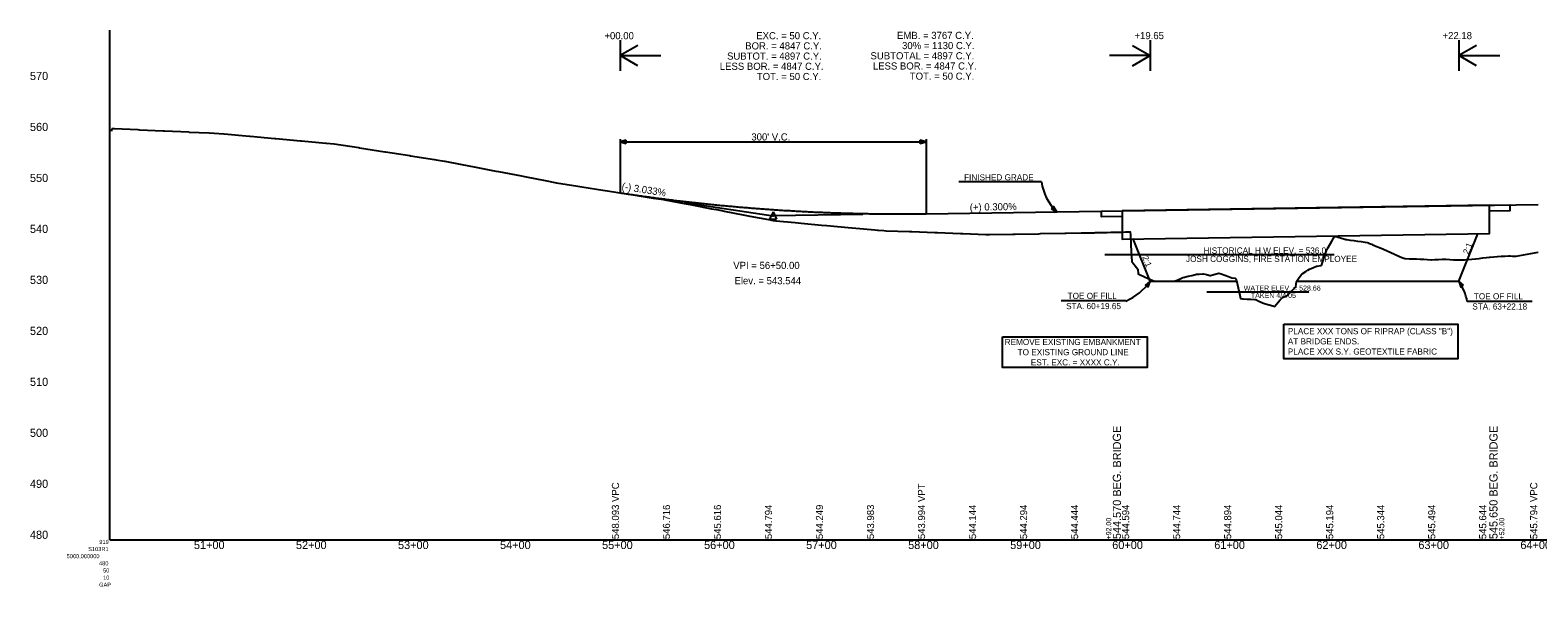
# Model space of a CAD drawing. Extents: x 1961504 to 1964196, y 1107046 to 1115093.
# Drawn here: x 1961506 to 1962983, y 1107046 to 1107593 of the extents above; entities that cross this region are included whole.
import ezdxf

# ---------------------------------------------------------------- set-up
doc = ezdxf.new("R2010")
doc.units = 0
for name, color, linetype in [('Level 40', 7, 'Continuous'), ('Level 41', 7, 'Continuous'), ('Level 42', 7, 'Continuous'), ('Level 43', 7, 'Continuous'), ('Level 45', 7, 'Continuous'), ('Level 49', 7, 'Continuous'), ('Level 58', 7, 'Continuous'), ('Level 63', 7, 'Continuous')]:
    doc.layers.add(name, color=color, linetype=linetype)

msp = doc.modelspace()

# ---------------------------------------------------------------- linework, layer by layer
at = {"layer": 'Level 40'}
for points in [[(1961585.6, 1107493.6), (1961585.8, 1107494.5), (1961586, 1107496.1), (1961588.4, 1107496), (1961611, 1107495), (1961612.8, 1107494.9), (1961636, 1107493.8), (1961637.2, 1107493.8), (1961661, 1107492.7), (1961661.5, 1107492.6), (1961681.2, 1107491.7), (1961686, 1107491.5), (1961686.1, 1107491.5), (1961695.5, 1107491), (1961695.9, 1107491), (1961720.5, 1107488.7), (1961721.1, 1107488.6), (1961745.5, 1107486.4), (1961746.3, 1107486.3), (1961770.4, 1107484.1), (1961771.5, 1107484), (1961795.4, 1107481.8), (1961795.9, 1107481.8), (1961803.4, 1107481.1), (1961827.7, 1107477.3), (1961828.4, 1107477.2), (1961853.3, 1107473.3), (1961853.3, 1107473.3), (1961853.7, 1107473.3), (1961877.7, 1107469.5), (1961878.4, 1107469.4), (1961902, 1107465.6), (1961903.4, 1107465.4), (1961911.6, 1107464.1), (1961912.1, 1107464), (1961913.7, 1107463.7), (1961937.1, 1107459.2), (1961939.2, 1107458.8), (1961962.1, 1107454.3), (1961964.7, 1107453.8), (1961987, 1107449.5), (1961990.2, 1107448.9), (1962012, 1107444.7), (1962019.8, 1107443.2), (1962021.4, 1107442.8), (1962042.3, 1107439.6), (1962046.4, 1107438.9), (1962067, 1107435.7), (1962071.5, 1107434.9), (1962091.6, 1107431.8), (1962096.5, 1107431), (1962116.3, 1107427.9), (1962121.5, 1107427), (1962126.4, 1107426.3), (1962127.5, 1107426.1), (1962146.7, 1107422.4), (1962152.4, 1107421.4), (1962154.2, 1107421.1), (1962173.5, 1107417.4), (1962178.4, 1107416.6), (1962183, 1107415.7), (1962185.7, 1107414.9), (1962204.4, 1107411.3), (1962210.8, 1107410.2), (1962229.2, 1107406.7), (1962233.9, 1107405.9), (1962236.4, 1107405.5), (1962255.4, 1107403.8), (1962261.4, 1107403.2), (1962281.3, 1107401.4), (1962286.3, 1107400.9), (1962307.4, 1107399.1), (1962311.3, 1107398.7), (1962333.4, 1107396.7), (1962336.2, 1107396.5), (1962336.7, 1107396.4), (1962342.3, 1107395.9), (1962344.7, 1107395.8), (1962367.3, 1107395), (1962369.7, 1107394.9), (1962392.3, 1107394), (1962394.7, 1107394), (1962417.3, 1107393.1), (1962419.7, 1107393), (1962442.3, 1107392.2), (1962442.8, 1107392.1), (1962445.9, 1107392), (1962468.8, 1107392.4), (1962470.9, 1107392.5), (1962494.1, 1107392.9), (1962495.9, 1107393), (1962519.5, 1107393.4), (1962520.9, 1107393.4), (1962535.7, 1107393.7), (1962539.3, 1107393.8), (1962542.9, 1107393.8), (1962544.8, 1107393.9), (1962545.9, 1107393.9), (1962545.9, 1107393.9), (1962546.5, 1107393.9), (1962548.4, 1107393.9)], [(1962548.4, 1107393.9), (1962549.5, 1107394), (1962550.2, 1107394), (1962553.8, 1107394), (1962557.4, 1107394.1), (1962561, 1107394.2), (1962564.6, 1107394.3), (1962568.2, 1107394.3), (1962571.8, 1107394.4), (1962573.4, 1107394.4), (1962574.2, 1107394.5), (1962575.4, 1107394.5), (1962579.1, 1107394.6), (1962582.7, 1107394.6), (1962583.7, 1107394.6), (1962583.8, 1107394.7), (1962583.9, 1107391.5), (1962584.2, 1107381.5), (1962585.3, 1107365.4), (1962586.3, 1107364.3), (1962589.9, 1107359.8), (1962591.2, 1107358.1), (1962591.5, 1107353.4), (1962593.5, 1107352.4), (1962597.1, 1107350.8), (1962598.5, 1107350.1), (1962600.7, 1107349.2), (1962604.3, 1107347.8), (1962606.9, 1107346.7), (1962607.9, 1107346.4), (1962608, 1107346.4), (1962611.6, 1107346.3), (1962615.2, 1107346.3), (1962618.8, 1107346.3), (1962622.4, 1107346.3), (1962626, 1107346.2), (1962626.8, 1107346.2), (1962627.9, 1107346.6), (1962629.6, 1107347.4), (1962633.2, 1107349.1), (1962635.4, 1107350), (1962636.8, 1107350.4), (1962640.4, 1107351.2), (1962644.1, 1107352), (1962647.7, 1107352.9), (1962648.7, 1107353.1), (1962651.3, 1107353.3), (1962654.9, 1107353.6), (1962655.4, 1107353.6), (1962658.5, 1107352.8), (1962662.1, 1107351.9), (1962662.3, 1107351.9), (1962665.7, 1107352.8), (1962669.3, 1107353.9), (1962670.6, 1107354.2), (1962673, 1107353.4), (1962676.6, 1107352.1), (1962680.2, 1107350.9), (1962683.4, 1107349.7), (1962683.8, 1107349.7), (1962686.7, 1107349.2), (1962687.3, 1107348.5), (1962687.4, 1107348.3), (1962687.8, 1107346.9), (1962691, 1107332.7), (1962691.8, 1107329.2), (1962693.7, 1107328.9), (1962694.6, 1107328.9), (1962698.2, 1107328.7), (1962701.8, 1107328.6), (1962705.5, 1107328.4), (1962706.8, 1107328.3), (1962709.1, 1107327.2), (1962712.7, 1107325.5), (1962713.4, 1107325.1), (1962716.3, 1107324.2), (1962719.9, 1107323.2), (1962723.5, 1107322.1), (1962725.1, 1107321.6), (1962727.1, 1107323.8), (1962730.7, 1107327.9), (1962732.9, 1107330.3), (1962734.3, 1107330.9), (1962737.5, 1107332.3), (1962738, 1107332.7), (1962741.6, 1107336.3), (1962745.2, 1107339.9), (1962746.1, 1107340.8), (1962746.8, 1107346.1), (1962748.8, 1107348.9), (1962751.3, 1107352.6), (1962752.4, 1107353.4), (1962756, 1107355.9), (1962757.8, 1107357.2), (1962759.6, 1107358), (1962763.2, 1107359.7), (1962766.4, 1107361.2), (1962766.9, 1107361.2), (1962767, 1107361.2), (1962770.5, 1107361.7), (1962771.1, 1107361.8)], [(1962771.1, 1107361.8), (1962774.1, 1107370.5), (1962776.5, 1107377.5), (1962777.7, 1107379.5), (1962781.3, 1107385.6), (1962784, 1107390.1), (1962784.3, 1107390.1), (1962784.9, 1107390), (1962786.7, 1107389.8), (1962788.5, 1107389.3), (1962792.1, 1107388.2), (1962795.1, 1107387.3), (1962795.7, 1107387.2), (1962799.4, 1107386.7), (1962803, 1107386.2), (1962806.6, 1107385.7), (1962810.2, 1107385.2), (1962813.8, 1107384.6), (1962816.1, 1107384.3), (1962817.4, 1107383.8), (1962817.4, 1107383.7), (1962817.5, 1107383.7), (1962819.3, 1107383), (1962820.7, 1107382.5), (1962821, 1107382.3), (1962824.6, 1107380.8), (1962828.2, 1107379.3), (1962831.9, 1107377.7), (1962835.5, 1107376.1), (1962839.1, 1107374.5), (1962842.7, 1107372.8), (1962844, 1107372.2), (1962846.3, 1107371.2), (1962847.8, 1107370.5), (1962849.9, 1107369.7), (1962853, 1107368.7), (1962853.5, 1107368.6), (1962857.1, 1107368.4), (1962860.7, 1107368.2), (1962860.7, 1107368.2), (1962864.4, 1107368.1), (1962868, 1107368), (1962868, 1107368), (1962871.6, 1107367.8), (1962875.2, 1107367.6), (1962878.8, 1107367.4), (1962878.9, 1107367.4), (1962882.4, 1107367.5), (1962886, 1107367.7), (1962889.6, 1107367.8), (1962893, 1107367.9), (1962893.3, 1107367.8), (1962896.9, 1107367.5), (1962900.5, 1107367.2), (1962900.6, 1107367.2), (1962904.1, 1107367.2), (1962907.7, 1107367.2), (1962910.5, 1107367.2), (1962911.3, 1107367.3), (1962914.9, 1107367.7), (1962918.5, 1107368), (1962922.1, 1107368.3), (1962922.3, 1107368.3), (1962925.8, 1107368.7), (1962929.4, 1107369.2), (1962933, 1107369.5), (1962935.5, 1107369.8), (1962936.6, 1107369.9), (1962940.2, 1107370.3), (1962943.8, 1107370.6), (1962943.8, 1107370.6), (1962947.4, 1107370.8), (1962951, 1107371), (1962954.6, 1107371.1), (1962956.2, 1107371.1), (1962958.3, 1107371), (1962961.6, 1107370.7), (1962961.9, 1107370.8), (1962965.5, 1107371.5), (1962969.1, 1107372.2), (1962972.7, 1107372.9), (1962976.3, 1107373.5), (1962979.9, 1107374.2), (1962981.5, 1107374.4), (1962983.5, 1107374.9)]]:
    msp.add_lwpolyline(points, dxfattribs=at)
at = {"layer": 'Level 41'}
for p, q in [((1962083.7, 1107485.5), (1962083.7, 1107433)), ((1962089.7, 1107484.5), (1962083.7, 1107483)), ((1962089.7, 1107484.5), (1962083.7, 1107483)), ((1962089.7, 1107481.5), (1962089.7, 1107484.5)), ((1962089.7, 1107481.5), (1962089.7, 1107484.5)), ((1962383.7, 1107483), (1962377.7, 1107484.5)), ((1962377.7, 1107484.5), (1962377.7, 1107481.5)), ((1962383.7, 1107485.5), (1962383.7, 1107412.5)), ((1962083.7, 1107483), (1962089.7, 1107481.5)), ((1962083.7, 1107483), (1962089.7, 1107481.5)), ((1962083.7, 1107483), (1962383.7, 1107483)), ((1962377.7, 1107481.5), (1962383.7, 1107483)), ((1962496.7, 1107443.7), (1962415.9, 1107443.7)), ((1962146.7, 1107423.5), (1962233.7, 1107410.3)), ((1962233.7, 1107414.3), (1962230.2, 1107407.3)), ((1962233.7, 1107414.3), (1962237.2, 1107407.3)), ((1962321.7, 1107411.6), (1962233.7, 1107410.3)), ((1962575.7, 1107415.4), (1962575.7, 1107387.6)), ((1962935.7, 1107393), (1962935.7, 1107420.8)), ((1962230.2, 1107407.3), (1962237.2, 1107407.3)), ((1962575.7, 1107387.6), (1962586.7, 1107387.7)), ((1962603.3, 1107346.2), (1962586.7, 1107387.7)), ((1962905.9, 1107346.2), (1962924.5, 1107392.8)), ((1962924.5, 1107392.8), (1962935.7, 1107393)), ((1962558.7, 1107372.6), (1962783.7, 1107372.6)), ((1962603.3, 1107346.2), (1962688, 1107346.2)), ((1962658.7, 1107335.9), (1962758.7, 1107335.9)), ((1962747, 1107346.2), (1962905.9, 1107346.2)), ((1962579.5, 1107326.9), (1962515.9, 1107326.9)), ((1962977.6, 1107326.5), (1962914, 1107326.5))]:
    msp.add_line(p, q, dxfattribs=at)
for points in [[(1962506.5, 1107417.3), (1962511.7, 1107414.3), (1962508.7, 1107419.5)], [(1962601.2, 1107340.6), (1962603.3, 1107346.2), (1962598.7, 1107342.4)], [(1962910.4, 1107342.3), (1962905.9, 1107346.2), (1962907.8, 1107340.6)], [(1962458.7, 1107291.7), (1962600.2, 1107291.7), (1962600.2, 1107261.7), (1962458.7, 1107261.7)], [(1962734.2, 1107304.3), (1962904.7, 1107304.3), (1962904.7, 1107270.3), (1962734.2, 1107270.3)]]:
    msp.add_lwpolyline(points, close=True, dxfattribs=at)
msp.add_circle((1962233.7, 1107410.3), 0.25, dxfattribs=at)
for centre, radius, start, end in [((1962549.9, 1107452.2), 53.9, 189.0843, 224.7278), ((1962555.7, 1107380.4), 58.6, 293.8972, 324.317), ((1962859.5, 1107315.4), 55.7, 11.5247, 33.6119)]:
    msp.add_arc(centre, radius, start, end, dxfattribs=at)
at = {"layer": 'Level 45'}
for p, q in [((1962083.7, 1107433), (1962083.7, 1107433)), ((1962383.7, 1107412.5), (1962983.7, 1107421.5)), ((1962575.7, 1107387.6), (1962935.7, 1107393))]:
    msp.add_line(p, q, dxfattribs=at)
for points in [[(1962555.7, 1107415.1), (1962575.7, 1107415.4), (1962575.7, 1107409.6), (1962555.7, 1107409.3)], [(1962935.7, 1107420.8), (1962955.7, 1107421.1), (1962955.7, 1107415.3), (1962935.7, 1107415)]]:
    msp.add_lwpolyline(points, close=True, dxfattribs=at)
msp.add_spline([(1962083.7, 1107433), (1962089.7, 1107432.1), (1962095.7, 1107431.2), (1962101.7, 1107430.4), (1962107.7, 1107429.5), (1962113.7, 1107428.7), (1962119.7, 1107427.9), (1962125.7, 1107427.1), (1962131.7, 1107426.4), (1962137.7, 1107425.6), (1962143.7, 1107424.9), (1962149.7, 1107424.2), (1962155.7, 1107423.5), (1962161.7, 1107422.9), (1962167.7, 1107422.2), (1962173.7, 1107421.6), (1962179.7, 1107421), (1962185.7, 1107420.4), (1962191.7, 1107419.9), (1962197.7, 1107419.3), (1962203.7, 1107418.8), (1962209.7, 1107418.3), (1962215.7, 1107417.8), (1962221.7, 1107417.4), (1962227.7, 1107416.9), (1962233.7, 1107416.5), (1962239.7, 1107416.1), (1962245.7, 1107415.7), (1962251.7, 1107415.4), (1962257.7, 1107415), (1962263.7, 1107414.7), (1962269.7, 1107414.4), (1962275.7, 1107414.1), (1962281.7, 1107413.9), (1962287.7, 1107413.6), (1962293.7, 1107413.4), (1962299.7, 1107413.2), (1962305.7, 1107413), (1962311.7, 1107412.9), (1962317.7, 1107412.7), (1962323.7, 1107412.6), (1962329.7, 1107412.5), (1962335.7, 1107412.4), (1962341.7, 1107412.4), (1962347.7, 1107412.3), (1962353.7, 1107412.3), (1962359.7, 1107412.3), (1962365.7, 1107412.3), (1962371.7, 1107412.4), (1962377.7, 1107412.4), (1962383.7, 1107412.5)], degree=3, dxfattribs=at)
at = {"layer": 'Level 49'}
msp.add_lwpolyline([(1962575.7, 1107415.4), (1962575.7, 1107387.6), (1962935.7, 1107393), (1962935.7, 1107420.8)], close=True, dxfattribs=at)
at = {"layer": 'Level 58'}
for p, q in [((1962083.7, 1107582.6), (1962083.7, 1107567.6)), ((1962101, 1107577.6), (1962083.7, 1107567.6)), ((1962586, 1107577.6), (1962603.3, 1107567.6)), ((1962603.3, 1107582.6), (1962603.3, 1107567.6)), ((1962905.9, 1107582.6), (1962905.9, 1107567.6)), ((1962923.2, 1107577.6), (1962905.9, 1107567.6)), ((1962083.7, 1107567.6), (1962083.7, 1107552.6)), ((1962083.7, 1107567.6), (1962123.7, 1107567.6)), ((1962101, 1107557.6), (1962083.7, 1107567.6)), ((1962603.3, 1107567.6), (1962563.3, 1107567.6)), ((1962586, 1107557.6), (1962603.3, 1107567.6)), ((1962603.3, 1107567.6), (1962603.3, 1107552.6)), ((1962905.9, 1107567.6), (1962905.9, 1107552.6)), ((1962905.9, 1107567.6), (1962945.9, 1107567.6)), ((1962923.2, 1107557.6), (1962905.9, 1107567.6))]:
    msp.add_line(p, q, dxfattribs=at)
at = {"layer": 'Level 63'}
for q in [(1961583.7, 1107592.6), (1964183.7, 1107092.6), (1961583.7, 1107092.6)]:
    msp.add_line((1961583.7, 1107092.6), q, dxfattribs=at)

# ---------------------------------------------------------------- texts
at = {"layer": 'Level 41'}
for s, height, p in [('+00.00', 7, (1962068.4, 1107583.6)), ('EXC. = 50 C.Y.', 7, (1962217.2, 1107583.6)), ('EMB. = 3767 C.Y.', 7, (1962355.2, 1107583.9)), ('+19.65', 7, (1962587.9, 1107583.7)), ('+22.18', 7, (1962889.8, 1107583.7)), ('BOR. = 4847 C.Y.', 7, (1962206.4, 1107573.6)), ('30% = 1130 C.Y.', 7, (1962360.1, 1107573.9)), ('LESS BOR. = 4847 C.Y.', 7, (1962181.5, 1107553.6)), ('SUBTOT. = 4897 C.Y.', 7, (1962188.6, 1107563.6)), ('SUBTOTAL = 4897 C.Y.', 7, (1962329.2, 1107563.9)), ('LESS BOR. = 4847 C.Y.', 7, (1962331.5, 1107553.9)), ('TOT. = 50 C.Y.', 7, (1962217.8, 1107543.6)), ('TOT. = 50 C.Y.', 7, (1962367.7, 1107543.9)), ("300' V.C.", 7, (1962212.4, 1107484.3)), ('FINISHED GRADE', 6, (1962420.9, 1107445.2)), ('VPI = 56+50.00', 7, (1962194.7, 1107358.3)), ('JOSH COGGINS, FIRE STATION EMPLOYEE', 6, (1962638.4, 1107365.2)), ("HISTORICAL H.W.ELEV. = 536.0'", 6, (1962655.6, 1107373.4)), ('Elev. = 543.544', 7, (1962195.9, 1107343.3)), ('WATER ELEV. = 528.66', 5, (1962695, 1107337)), ('STA. 60+19.65', 6, (1962520.9, 1107318.9)), ('TOE OF FILL', 6, (1962522.4, 1107328.9)), ('TAKEN 4/4/05', 5, (1962702, 1107329.9)), ('STA. 63+22.18', 6, (1962919, 1107318.5)), ('TOE OF FILL', 6, (1962920.5, 1107328.5)), ('PLACE XXX TONS OF RIPRAP (CLASS "B")', 6, (1962738.2, 1107294.3)), ('REMOVE EXISTING EMBANKMENT', 6, (1962460.7, 1107283.7)), ('TO EXISTING GROUND LINE', 6, (1962473.4, 1107273.7)), ('AT BRIDGE ENDS.', 6, (1962738.2, 1107284.3)), ('PLACE XXX S.Y. GEOTEXTILE FABRIC', 6, (1962738.2, 1107274.3)), ('EST. EXC. = XXXX C.Y.', 6, (1962486.3, 1107263.7))]:
    msp.add_text(s, height=height, dxfattribs=at).set_placement(p)
for s, height, rotation, p in [('(-) 3.033%', 7, 351.3774, (1962085, 1107436)), ('(+) 0.300%', 7, 0.8594, (1962426.5, 1107415.4)), ('2:1', 6, 68.1986, (1962915.2, 1107372.2)), ('2:1', 6, 291.8014, (1962595.4, 1107369.9))]:
    msp.add_text(s, height=height, rotation=rotation, dxfattribs=at).set_placement(p)
at = {"layer": 'Level 42'}
for s, p in [('570', (1961505.4, 1107543.6)), ('560', (1961505.4, 1107493.6)), ('550', (1961505.4, 1107443.6)), ('540', (1961505.4, 1107393.6)), ('530', (1961505.4, 1107343.6)), ('520', (1961505.4, 1107293.6)), ('510', (1961505.4, 1107243.6)), ('500', (1961505.4, 1107193.6)), ('490', (1961505.4, 1107143.6)), ('480', (1961505.4, 1107093.6)), ('51+00', (1961666.1, 1107083.6)), ('52+00', (1961766.1, 1107083.6)), ('53+00', (1961866.1, 1107083.6)), ('54+00', (1961966.1, 1107083.6)), ('55+00', (1962066.1, 1107083.6)), ('56+00', (1962166.1, 1107083.6)), ('57+00', (1962266.1, 1107083.6)), ('58+00', (1962366.1, 1107083.6)), ('59+00', (1962466.1, 1107083.6)), ('60+00', (1962566.1, 1107083.6)), ('61+00', (1962666.1, 1107083.6)), ('62+00', (1962766.1, 1107083.6)), ('63+00', (1962866.1, 1107083.6)), ('64+00', (1962966.1, 1107083.6))]:
    msp.add_text(s, height=8, dxfattribs=at).set_placement(p)
at = {"layer": 'Level 43'}
for s, height, p in [('544.570 BEG. BRIDGE', 8, (1962574.7, 1107093.3)), ('545.650 BEG. BRIDGE', 8, (1962943.7, 1107093.3)), ('548.093 VPC', 7, (1962082.7, 1107093.3)), ('543.994 VPT', 7, (1962382.7, 1107093.3)), ('545.794 VPC', 7, (1962982.7, 1107093.3)), ('548.093', 7, (1962082.7, 1107093.3)), ('546.716', 7, (1962132.7, 1107093.3)), ('545.616', 7, (1962182.7, 1107093.3)), ('544.794', 7, (1962232.7, 1107093.3)), ('544.249', 7, (1962282.7, 1107093.3)), ('543.983', 7, (1962332.7, 1107093.3)), ('543.994', 7, (1962382.7, 1107093.3)), ('544.144', 7, (1962432.7, 1107093.3)), ('544.294', 7, (1962482.7, 1107093.3)), ('544.444', 7, (1962532.7, 1107093.3)), ('544.594', 7, (1962582.7, 1107093.3)), ('544.744', 7, (1962632.7, 1107093.3)), ('544.894', 7, (1962682.7, 1107093.3)), ('545.044', 7, (1962732.7, 1107093.3)), ('545.194', 7, (1962782.7, 1107093.3)), ('545.344', 7, (1962832.7, 1107093.3)), ('545.494', 7, (1962882.7, 1107093.3)), ('545.644', 7, (1962932.7, 1107093.3)), ('545.794', 7, (1962982.7, 1107093.3)), ('+92.00', 5, (1962565.1, 1107093)), ('+52.00', 5, (1962950.3, 1107093))]:
    msp.add_text(s, height=height, rotation=90, dxfattribs=at).set_placement(p)
at = {"layer": 'Level 63'}
for s, p in [('S103R1', (1961562.5, 1107081.6)), ('919', (1961573.4, 1107088.6)), ('5000.000000', (1961541.3, 1107074.6)), ('480', (1961573.1, 1107067.6)), ('50', (1961577.1, 1107060.6)), ('10', (1961577.1, 1107053.6)), ('GAP', (1961573.2, 1107046.6))]:
    msp.add_text(s, height=4, dxfattribs=at).set_placement(p)

doc.saveas('drawing.dxf')
